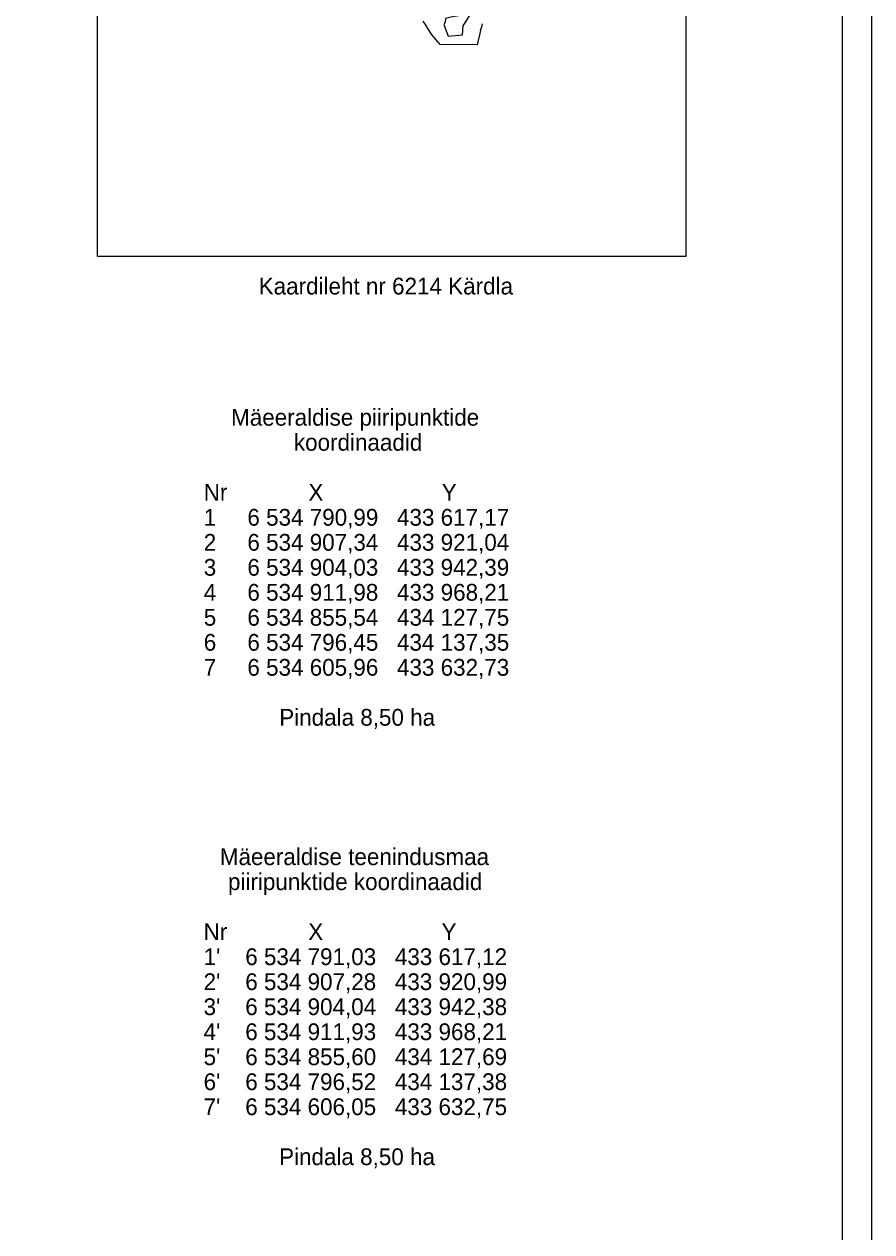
# Model space of a CAD drawing. Extents: x 433497 to 434382, y 6534486 to 6534993.
# Drawn here: x 434237.5 to 434381.6, y 6534671.5 to 6534876.8 of the extents above; entities that cross this region are included whole.
import ezdxf

# ---------------------------------------------------------------- set-up
doc = ezdxf.new("R2010")
doc.units = 0
doc.layers.add('VORMISTUS', color=7, linetype='Continuous')
doc.layers.add('VWX2_MV_MAARDLA_ASUKOHT', color=7, linetype='Continuous')

msp = doc.modelspace()

# ---------------------------------------------------------------- linework, layer by layer
at = {"layer": 'VORMISTUS'}
for points in [[(433496.62, 6534983.07), (433496.62, 6534486.03), (434381.62, 6534486.03), (434381.62, 6534983.07)], [(434376.62, 6534978.07), (433516.62, 6534978.07), (433516.62, 6534491.03), (434376.62, 6534491.03)], [(434250, 6534937.27), (434350, 6534937.27), (434350, 6534837.27), (434250, 6534837.27)]]:
    msp.add_lwpolyline(points, close=True, dxfattribs=at)
at = {"layer": 'VWX2_MV_MAARDLA_ASUKOHT'}
msp.add_lwpolyline([(434308.85, 6534876.71), (434309.59, 6534874.75), (434312.06, 6534875), (434312.17, 6534876.5), (434312.8, 6534877.48), (434313.43, 6534878.49), (434311.03, 6534878.14), (434310.08, 6534877.96), (434309.14, 6534877.73), (434309.09, 6534877.11)], close=True, dxfattribs=at)
msp.add_lwpolyline([(434315.38, 6534876.83), (434315.28, 6534876.29), (434315.07, 6534875.72), (434315.12, 6534875.72), (434314.53, 6534873.28), (434308.25, 6534873.31), (434308.25, 6534873.31), (434308.25, 6534873.31), (434307.5, 6534874.18), (434306.77, 6534875.08), (434306.18, 6534876.08), (434305.76, 6534876.76), (434305.35, 6534877.28)], dxfattribs=at)

# ---------------------------------------------------------------- texts
at = {"layer": 'VORMISTUS'}
msp.add_text('Kaardileht nr 6214 Kärdla', height=2.85, rotation=0.0038, dxfattribs=at).set_placement((434277.41, 6534830.84))
for s, p in [('Mäeeraldise piiripunktide', (434272.72, 6534808.54)), ('koordinaadid', (434283.39, 6534804.29)), ('Nr             X                   Y', (434268.07, 6534795.79)), ('1     6 534 790,99   433 617,17', (434268.07, 6534791.54)), ('2     6 534 907,34   433 921,04', (434268.07, 6534787.29)), ('3     6 534 904,03   433 942,39', (434268.07, 6534783.04)), ('4     6 534 911,98   433 968,21', (434268.07, 6534778.79)), ('5     6 534 855,54   434 127,75', (434268.07, 6534774.54)), ('6     6 534 796,45   434 137,35', (434268.07, 6534770.29)), ('7     6 534 605,96   433 632,73', (434268.07, 6534766.04)), ('Pindala 8,50 ha', (434280.9, 6534757.54)), ('Mäeeraldise teenindusmaa', (434270.8, 6534733.85)), ('piiripunktide koordinaadid', (434272.19, 6534729.6)), ('Nr             X                   Y', (434268.04, 6534721.1)), ("1'    6 534 791,03   433 617,12", (434268.04, 6534716.85)), ("2'    6 534 907,28   433 920,99", (434268.04, 6534712.6)), ("3'    6 534 904,04   433 942,38", (434268.04, 6534708.35)), ("4'    6 534 911,93   433 968,21", (434268.04, 6534704.1)), ("5'    6 534 855,60   434 127,69", (434268.04, 6534699.85)), ("6'    6 534 796,52   434 137,38", (434268.04, 6534695.6)), ("7'    6 534 606,05   433 632,75", (434268.04, 6534691.35)), ('Pindala 8,50 ha', (434280.87, 6534682.85))]:
    msp.add_text(s, height=2.85, dxfattribs=at).set_placement(p)

doc.saveas('drawing.dxf')
